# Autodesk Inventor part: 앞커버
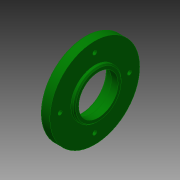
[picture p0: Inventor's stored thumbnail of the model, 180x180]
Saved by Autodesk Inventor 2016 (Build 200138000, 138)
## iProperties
Created: 2015-09
Part Number: 앞커버
Material: 알루미늄 6061
Document SubType Name: Modeling
Designer: mduedu
Density: 2.71 g/cm^3
Mass: 58.9874 g
Surface Area: 98.7754 cm^2
Volume: 21.7666 cm^3
Appearance: 진녹색
Author: mduedu
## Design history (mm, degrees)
sketch "스케치1"
  geometry: L1 (-8.5, 67)-(-11.5, 67); L2 (-11.5, 67)-(-11.5, 84.5); L3 (-11.5, 84.5)-(-19.5, 84.5); L4 (-19.5, 84.5)-(-19.5, 70.5); L5 (-22.5, 70.5)-(-22.5, 58); L6 (-22.5, 58)-(-8.5, 58); L7 (-8.5, 58)-(-8.5, 67); L8 (-79.5, 39.5)-(-79.5, 54.5) reference; L9 (48.5, 54.5)-(48.5, 39.5) reference; L10 (-79.5, 47)-(48.5, 47); L11 (-19.5, 70.5)-(-22.5, 70.5); 3 further points
  constraints: 18 end point, 6 parallel, 4 midpoint, 1 horizontal, 1 perpendicular, 1 vertical alignment
  dimensions: "d0" = 14 distance between parallel lines of L7 L5; "d2" = 22 diameter of L6 L10; "d3" = 40 diameter of L1 L10; "d5" = 3 distance of L1.start L1.end; "d6" = 75 diameter of L3 L10; "d7" = 8 distance of L2.end L3.end; "d8" = 47 diameter of L4.end L10
revolve "회전1" sketch "스케치1" stored, may be unused: angle "d4" = 90 deg
sketch "스케치2"
  geometry: C1 r 37.5 at (0, 0) reference; 2 further points
  constraints: 1 coincident
hole "구멍1" sketch "스케치2" at (0, 0) diameter "d11" = 33; stored, may be unused: countersink angle "d15" = 90 deg, drill point angle "d17" = 0 deg; dims "d12" = 6, "d13" = 4, "d14" = 2, "d16" = 3
fillet "모깎기1" dims "d18" = 3
fillet "모깎기2" dims "d19" = 1
sketch "스케치3"
  geometry: C1 r 37.5 at (0, 0) reference; 2 further points
  constraints: 1 coincident
hole "구멍2" sketch "스케치3" at (0, 0) diameter "d20" = 32; stored, may be unused: countersink angle "d24" = 90 deg, drill point angle "d26" = 0 deg; dims "d21" = 6, "d22" = 4, "d23" = 2, "d25" = 8.3
fillet "모깎기3" dims "d27" = 0.4
chamfer "모따기1" distance "d28" = 0.8; stored, may be unused: second distance "d29" = 2, angle "d30" = 30 deg
sketch "스케치7" dims "d56" = 58
  geometry: C1 r 37.5 at (0, 0) reference; 5 further points
  constraints: 2 vertical alignment, 1 coincident, 7 other
  dimensions: "d59" = 360 deg dimension on C1.centre point (0, 29) (derived)
hole "구멍4" sketch "스케치7" at (0, 29), (-29, 0), (0, -29), (29, 0) diameter "d48" = 3.4; stored, may be unused: countersink angle "d52" = 90 deg, drill point angle "d54" = 0 deg; dims "d49" = 6, "d50" = 6.5, "d51" = 3.4, "d53" = 8
chamfer "모따기2" distance "d61" = 1; stored, may be unused: second distance "d62" = 2, angle "d63" = 45 deg
node "솔리드1"
node "참조1"
node "참조2"
